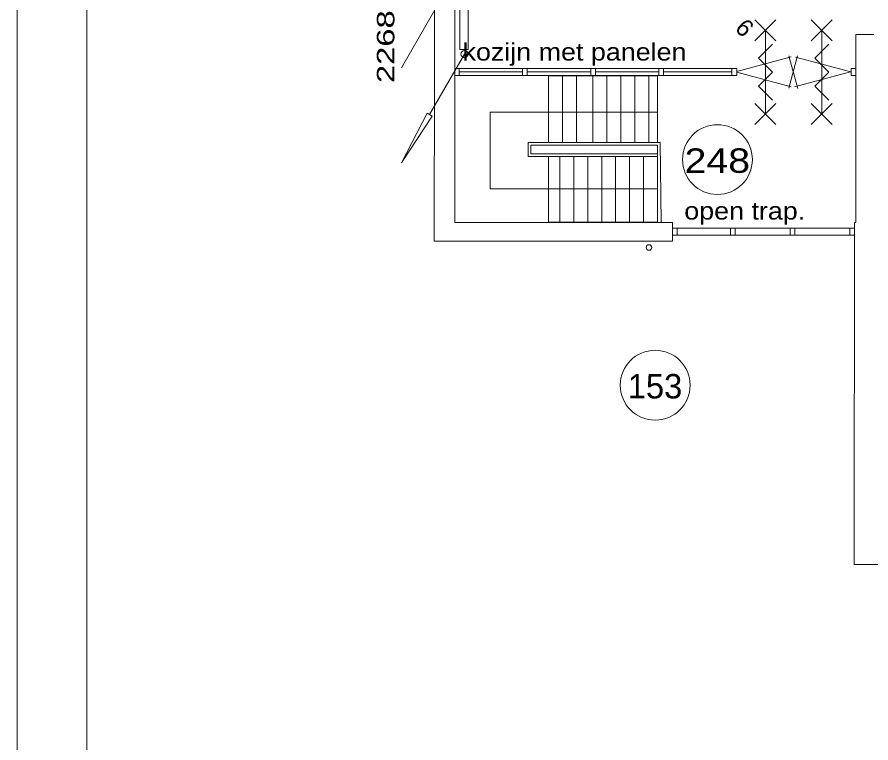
# Model space of a CAD drawing. Extents: x 295824 to 414724, y 24924 to 109024.
# Drawn here: x 295824 to 308047, y 84999 to 95396 of the extents above; entities that cross this region are included whole.
import ezdxf
from ezdxf.enums import TextEntityAlignment as Align

# ---------------------------------------------------------------- set-up
doc = ezdxf.new("R2010")
doc.units = 0
doc.header["$LTSCALE"] = 100
for name, color, linetype, lineweight in [('1', 7, 'Continuous', 13), ('16', 7, 'Continuous', 13), ('61', 7, 'Continuous', 13)]:
    doc.layers.add(name, color=color, linetype=linetype, lineweight=lineweight)

msp = doc.modelspace()

# ---------------------------------------------------------------- linework, layer by layer
at = {"layer": '1'}
msp.add_line((295823.6, 109023.8), (295823.6, 24923.8), dxfattribs=at)
msp.add_lwpolyline([(304995.6, 108023.8), (296823.6, 108023.8), (296823.6, 25923.8), (304995.6, 25923.8)], dxfattribs=at)
at = {"layer": '16'}
for p, q in [((301324.6, 94667.1), (301824.6, 95533.1)), ((302228.5, 94864.8), (301728.5, 93998.8))]:
    msp.add_line(p, q, dxfattribs=at)
for points in [[(302281.5, 96151.6), (302281.5, 94932.2), (302163.6, 94932.2), (302163.6, 96151.6)], [(301328.5, 93305.8), (301692.5, 94019.8), (301764.5, 93977.8)]]:
    msp.add_lwpolyline(points, close=True, dxfattribs=at)
msp.add_circle((302228.5, 94865.1), 50, dxfattribs=at)
at = {"layer": '61'}
for p, q in [((302090.1, 94558.1), (302090.1, 97322)), ((306687.3, 95355.9), (306387.3, 95055.9)), ((306387.3, 95355.9), (306687.3, 95055.9)), ((307493.3, 95355.9), (307193.3, 95055.9)), ((307193.3, 95355.9), (307493.3, 95055.9)), ((306537.3, 94005.9), (306537.3, 95205.9)), ((307343.3, 94005.9), (307343.3, 95205.9)), ((306127.9, 94617), (306903.9, 94824.9)), ((306994, 94838.6), (306870.9, 94379.1)), ((306998.8, 94372.3), (306873, 94842)), ((306968.5, 94823.2), (307758.5, 94611.5)), ((302090.5, 94658.1), (306126.4, 94658.1)), ((302152.3, 94557.9), (302152.3, 94657.9)), ((302153.3, 94611.3), (303061.3, 94611.3)), ((303060.3, 94557.9), (303060.3, 94657.9)), ((303127.3, 94557.9), (303127.3, 94657.9)), ((303127.6, 94611.3), (304035.6, 94611.3)), ((304035.3, 94557.9), (304035.3, 94657.9)), ((304101.9, 94611.3), (305009.9, 94611.3)), ((304102.3, 94557.9), (304102.3, 94657.9)), ((305010.3, 94557.9), (305010.3, 94657.9)), ((305077.3, 94557.9), (305077.3, 94657.9)), ((305078.6, 94611.3), (306052.9, 94611.3)), ((306055.9, 94557.9), (306055.9, 94657.9)), ((306126.4, 94558.1), (306126.4, 94658.1)), ((306955.3, 94396.3), (307756.8, 94611)), ((307764.7, 94558.1), (307764.7, 94658.1)), ((307764.7, 94658.1), (307831.7, 94658.1)), ((307831.7, 94558.1), (307831.7, 94658.1)), ((307832.8, 94655.7), (307832.8, 92454.5)), ((302090.1, 92454.5), (302090.1, 94554.5)), ((302090.5, 94558.1), (306126.4, 94558.1)), ((303433.4, 93599.7), (303433.4, 94552)), ((303633.4, 93602.1), (303633.4, 94552)), ((303833.4, 93609.5), (303833.4, 94552)), ((304065.8, 93599.7), (304065.8, 94546.5)), ((304265.8, 93599.7), (304265.8, 94552.7)), ((304465.8, 93599.7), (304465.8, 94552.7)), ((304665.8, 93599.7), (304665.8, 94552.7)), ((304865.8, 93599.7), (304865.8, 94552.7)), ((306127.9, 94606.3), (306906.8, 94397.6)), ((307764.7, 94558.1), (307831.7, 94558.1)), ((306687.3, 94155.9), (306387.3, 93855.9)), ((306387.3, 94155.9), (306687.3, 93855.9)), ((307493.3, 94155.9), (307193.3, 93855.9)), ((307193.3, 94155.9), (307493.3, 93855.9)), ((303983.1, 94033.5), (304996.9, 94033.5)), ((303433.4, 93599.7), (303140.1, 93599.7)), ((303140.1, 93599.7), (303140.1, 93397.7)), ((303180.1, 93559.7), (304991.2, 93559.7)), ((303180.1, 93559.7), (303180.1, 93437.7)), ((303865.8, 93599.7), (305030.8, 93599.7)), ((304991.2, 93559.7), (304992.8, 93397.7)), ((305030.8, 93599.7), (305042.2, 92457.9)), ((303433.4, 93397.7), (303140.1, 93397.7)), ((303180.1, 93437.7), (304992.8, 93437.7)), ((303592.8, 92459.8), (303592.8, 93397.7)), ((303792.8, 92459.8), (303792.8, 93397.7)), ((303992.8, 92459.8), (303992.8, 93397.7)), ((304192.8, 92459.8), (304192.8, 93397.7)), ((304392.8, 92459.8), (304392.8, 93397.7)), ((304592.8, 92459.8), (304592.8, 93397.7)), ((304792.8, 92459.8), (304792.8, 93397.7)), ((304992.8, 92459.8), (304992.8, 93397.7)), ((305206.2, 92454.5), (302090.1, 92454.5)), ((305206.2, 92184.5), (305206.2, 92454.5)), ((307806, 87553.4), (307811.7, 92454.5)), ((307832.8, 92454.5), (307811.7, 92454.5)), ((305206.6, 92272.5), (305206.6, 92373.4)), ((305206.6, 92373.4), (307811.6, 92373.4)), ((305273.6, 92273.4), (305273.6, 92373.4)), ((306035.3, 92273.4), (306035.3, 92373.4)), ((306102.3, 92273.4), (306102.3, 92373.4)), ((306889.3, 92273.4), (306889.3, 92373.4)), ((306956.6, 92272.5), (306956.6, 92373.4)), ((307740.6, 92373.4), (307807.6, 92373.4)), ((307743.6, 92272.5), (307743.6, 92373.4)), ((307810.6, 92272.5), (307810.6, 92373.4)), ((305206.2, 92184.5), (301796.6, 92184.5)), ((305206.6, 92272.5), (307810.6, 92272.5)), ((326233, 87553.4), (307806, 87553.4))]:
    msp.add_line(p, q, dxfattribs=at)
for points in [[(301796.6, 92184.5), (301820.1, 104417.6), (332210.1, 104417.6)], [(308090.1, 95148.4), (307832.8, 95148.4), (307832.8, 94654.5)], [(306637.3, 94205.9), (306437.3, 94405.9), (306637.3, 94605.9), (306437.3, 94805.9), (306637.3, 95005.9)], [(307443.3, 94205.9), (307243.3, 94405.9), (307443.3, 94605.9), (307243.3, 94805.9), (307443.3, 95005.9)], [(304990.8, 93599.7), (303433.4, 93599.7), (303433.4, 94552), (304122.8, 94552)], [(304990.8, 93599.7), (304990.8, 94552.7), (304123.5, 94552.7)], [(304992.8, 92935.9), (302596, 92935.9), (302596, 94032.5), (303992.5, 94032.5)]]:
    msp.add_lwpolyline(points, dxfattribs=at)
msp.add_lwpolyline([(304992.8, 92459.8), (303433.4, 92459.8), (303433.4, 93397.7), (304992.8, 93397.7)], close=True, dxfattribs=at)
for centre, radius in [((305849.6, 93354.6), 500), ((304869.5, 92095.7), 40), ((304958.7, 90122.7), 500)]:
    msp.add_circle(centre, radius, dxfattribs=at)

# ---------------------------------------------------------------- texts
at = {"layer": '16', "width": 1.4}
msp.add_text('2268-285-I', height=250, rotation=90, dxfattribs=at).set_placement((301224.6, 94451))
at = {"layer": '61'}
msp.add_text('6', height=250, rotation=315, dxfattribs=at).set_placement((306086.5, 95220))
at = {"layer": '61', "width": 1.15}
for s, p in [('kozijn met panelen', (302200.9, 94772.8)), ('open trap.', (305375.1, 92495.4))]:
    msp.add_text(s, height=250, dxfattribs=at).set_placement(p)
at = {"layer": '61', "width": 1.2}
msp.add_text('248', height=350, dxfattribs=at).set_placement((305848.1, 93164.7), align=Align.CENTER)
at = {"layer": '61'}
msp.add_text('153', height=350, dxfattribs=at).set_placement((304955.8, 89932.8), align=Align.CENTER)

doc.saveas('drawing.dxf')
